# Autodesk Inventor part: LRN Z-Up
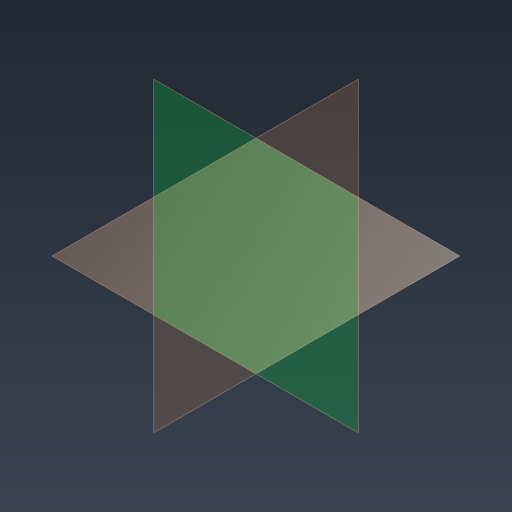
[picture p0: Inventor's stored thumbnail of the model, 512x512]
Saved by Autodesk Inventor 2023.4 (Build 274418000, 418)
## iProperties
Created: 2023-03
Part Number: LRN Z-Up
Material: Generic
Document SubType Name: Modeling
Designer: g4ecdbje
Density: 1 g/cm^3
Appearance: Default
Author: g4ecdbje
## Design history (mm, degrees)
